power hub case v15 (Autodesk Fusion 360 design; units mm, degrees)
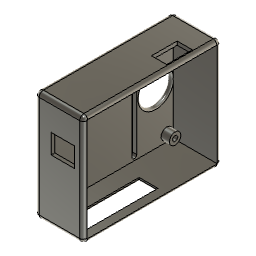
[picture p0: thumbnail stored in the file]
sketch "草图1" plane through (0, 0, 0) normal (1, 0, 0) x axis (0, 1, 0)
  line L1 (-27.76, -19.4335) -> (-27.76, 28.5665)
  line L2 (33.24, 28.5665) -> (33.24, -19.4335)
  line L3 (33.24, -19.4335) -> (-27.76, -19.4335)
  line L4 (-27.76, 28.5665) -> (33.24, 28.5665)
  line L5 (35.49, -21.6835) -> (-30.01, -21.6835)
  line L6 (35.49, 30.8165) -> (35.49, -21.6835)
  line L7 (-30.01, 30.8165) -> (35.49, 30.8165)
  line L8 (-30.01, -21.6835) -> (-30.01, 30.8165)
  line L9 (33.74, -19.9335) -> (-28.26, -19.9335)
  line L10 (33.74, 29.0665) -> (33.74, -19.9335)
  line L11 (-28.26, 29.0665) -> (33.74, 29.0665)
  line L12 (-28.26, -19.9335) -> (-28.26, 29.0665)
  circle C1 centre (30.68, -16.4685) radius 1.225
  circle C2 centre (-17.36, 25.6015) radius 1.225
  circle C3 centre (30.68, 25.6015) radius 1.225
  circle C4 centre (-17.36, -16.4685) radius 1.225
  point P2 (-27.76, 28.5665)
  point P3 (-27.76, -19.4335)
  point P5 (33.24, 28.5665)
  point P6 (-17.36, 25.6015)
  point P9 (30.68, 25.6015)
  point P7 (-17.36, -16.4685)
  point P8 (30.68, -16.4685)
  equal C2 C3
  equal C1 C3
  equal C1 C4
  dimension "d1" distance P2 P3 = 48
  dimension "d2" distance P2 P5 = 61 (= "57.00 mm + 4 mm")
  dimension "d3" distance P6 P9 = 48.04
  dimension "d4" distance P6 P7 = 42.07
  dimension "d5" distance P6 L4 = 2.965
  dimension "d6" distance P6 L1 = 10.4 (= "6.4 mm + 4 mm")
  dimension "d7" = 2.25
  dimension "d8" diameter C2 = 2.45
  dimension "d19" distance P7 P8 = 48.04
  dimension "d20" = 0.5
extrude "拉伸1" new body sketch "草图1" profile of C1 L1 L2 L3 C2 C3 L4 C4 along normal blind 2
extrude "拉伸2" add sketch "草图1" profile of L8 L5 L7 L6 L12 L11 L10 L9 along normal blind 23 (= "2.00 mm + 4 mm + 17 mm")
sketch "草图2" plane through (2, 0, 0) normal (1, 0, 0) x axis (0, 1, 0)
  line L1 (-28.26, -19.9335) -> (-28.26, 29.0665)
  line L2 (33.74, -19.9335) -> (-28.26, -19.9335)
  line L3 (33.74, 29.0665) -> (33.74, -19.9335)
  line L4 (-28.26, 29.0665) -> (33.74, 29.0665)
  circle C1 centre (-17.36, -16.4685) radius 1.225
  circle C2 centre (-17.36, 25.6015) radius 1.225
  circle C3 centre (30.68, 25.6015) radius 1.225
  circle C4 centre (30.68, -16.4685) radius 1.225
  circle C5 centre (-17.36, 25.6015) radius 2.725
  circle C6 centre (30.68, 25.6015) radius 2.725
  circle C7 centre (-17.36, -16.4685) radius 2.725
  circle C8 centre (30.68, -16.4685) radius 2.725
  dimension "d13" = 1.5
  dimension "d14" = 1.5
  dimension "d15" = 1.5
  dimension "d16" = 1.5
extrude "拉伸3" add sketch "草图2" profile of C1 C2 C3 C4 C5 C6 C7 C8 along normal blind 4
sketch "草图3" plane through (0, 0, -21.6835) normal (0, 0, -1) x axis (1, 0, 0)
  line L1 (0, -35.49) -> (0, 30.01)
  line L2 (23, -35.49) -> (0, -35.49)
  line L3 (23, 30.01) -> (23, -35.49)
  line L4 (0, 30.01) -> (23, 30.01)
  line L5 (6, 30.01) -> (6, -35.49)
  line L6 (6, -35.49) -> (23, -35.49)
  line L7 (23, 30.01) -> (23, -35.49)
  line L8 (23, 30.01) -> (6, 30.01)
  line L9 (19, 26.01) -> (10, 26.01)
  line L10 (19, 26.01) -> (19, -31.49)
  line L11 (10, -31.49) -> (19, -31.49)
  line L12 (10, 26.01) -> (10, -31.49)
  line L13 (10, -9.49) -> (19, -9.49)
  point P6 (6, -35.49)
  point P7 (6, 30.01)
  point P4 (23, -35.49)
  point P8 (23, -35.49)
  point P5 (23, 30.01)
  point P9 (23, 30.01)
  point P14 (19, -9.49)
  point P15 (10, -9.49)
  coincident L2 P6
  coincident L4 P7
  perpendicular L4 L5
  coincident P4 P8
  coincident P5 P9
  coincident L10 P14
  coincident L12 P15
  perpendicular L12 L13
  dimension "d21" distance L1 L5 = 6
  dimension "d22" = 4
  dimension "d25" distance L11 L13 = 22
extrude "拉伸4" cut sketch "草图3" profile of L10 L9 L12 L13 against normal blind 2
sketch "草图4" plane through (0, 0, 30.8165) normal (0, 0, 1) x axis (-1, 0, 0)
  line L1 (0, 30.01) -> (0, -35.49)
  line L2 (-23, 30.01) -> (0, 30.01)
  line L3 (-23, -35.49) -> (-23, 30.01)
  line L4 (0, -35.49) -> (-23, -35.49)
  line L5 (-18.8, -22.037) -> (-15.6, -22.037)
  line L6 (-18.8, -13.837) -> (-18.8, -22.037)
  line L7 (-15.6, -13.837) -> (-18.8, -13.837)
  line L8 (-15.6, -22.037) -> (-15.6, -13.837)
  line L9 (-13.6, -24.037) -> (-13.6, -11.837)
  line L10 (-20.8, -24.037) -> (-13.6, -24.037)
  line L11 (-20.8, -11.837) -> (-20.8, -24.037)
  line L12 (-13.6, -11.837) -> (-20.8, -11.837)
  point P6 (-15.6, -22.037)
  point P7 (-18.8, -22.037)
  point P8 (-18.8, -13.837)
  horizontal L5
  vertical L6
  horizontal L7
  vertical L8
  dimension "d26" distance L4 P6 = 13.453 (= "11.453 mm + 2 mm")
  dimension "d27" distance L1 L8 = 15.6 (= "9.6 mm + 4 mm + 2 mm")
  dimension "d28" distance P7 P8 = 8.2
  dimension "d29" distance P6 P7 = 3.2
  dimension "d30" = -2
extrude "拉伸5" cut sketch "草图4" profile of L9 L10 L11 L12 against normal blind 2
sketch "草图5" plane through (0, 0, 0) normal (-1, 0, 0) x axis (0, -1, 0)
  line L1 (30.01, 30.8165) -> (30.01, -21.6835)
  line L2 (-35.49, 30.8165) -> (30.01, 30.8165)
  line L3 (-35.49, -21.6835) -> (-35.49, 30.8165)
  line L4 (30.01, -21.6835) -> (-35.49, -21.6835)
  line L5 (-2.74, -21.6835) -> (-2.74, 30.8165)
  line L6 (30.01, 4.5665) -> (-2.74, 4.5665)
  line L7 (8.635, -17.9335) -> (8.635, 27.0665)
  line L8 (10.885, 27.0665) -> (10.885, -17.9335)
  line L9 (-16.365, 27.0665) -> (-16.365, -17.9335)
  line L10 (-14.115, -17.9335) -> (-14.115, 27.0665)
  line L11 (-25.49, 4.5665) -> (-2.74, 4.5665)
  circle C1 centre (-30.68, -16.4685) radius 1.225
  circle C2 centre (17.36, 25.6015) radius 1.225
  circle C3 centre (-30.68, 25.6015) radius 1.225
  circle C4 centre (17.36, -16.4685) radius 1.225
  circle C5 centre (9.76, 27.0665) radius 1.125
  circle C6 centre (9.76, -17.9335) radius 1.125
  circle C7 centre (-15.24, 27.0665) radius 1.125
  circle C8 centre (-15.24, -17.9335) radius 1.125
  circle C9 centre (-25.49, 4.5665) radius 7.5
  point P10 (-2.74, 30.8165)
  point P11 (-2.74, -21.6835)
  point P13 (-2.74, 4.5665)
  point P14 (30.01, 4.5665)
  point P16 (8.635, 27.0665)
  point P17 (8.635, -17.9335)
  point P18 (10.885, -17.9335)
  point P19 (10.885, 27.0665)
  point P15 (9.76, -17.9335)
  point P22 (-15.24, -17.9335)
  point P21 (-14.115, 27.0665)
  point P25 (-14.115, -17.9335)
  point P24 (-16.365, -17.9335)
  point P23 (-16.365, 27.0665)
  point P27 (-25.49, 4.5665)
  point P28 (-25.49, 4.5665)
  point P12 (9.76, 27.0665)
  point P20 (-15.24, 27.0665)
  midpoint L2 P10
  midpoint L4 P11
  midpoint L5 P13
  midpoint L1 P14
  symmetric C5 L6 C6
  coincident C5 P16
  coincident C6 P17
  coincident C6 P18
  coincident C5 P19
  vertical L8
  tangent C5 L8
  tangent C6 L7
  tangent C5 L7
  symmetric L5 C5 C7
  symmetric L5 P15 P22
  symmetric L5 P16 P21
  symmetric L5 P17 P25
  symmetric L5 P18 P24
  symmetric L5 P19 P23
  symmetric L5 C6 C8
  perpendicular L5 L11
  coincident P27 P28
  dimension "d33" diameter C5 = 2.25
  dimension "d34" distance P12 P20 = 25
  dimension "d35" distance P18 P19 = 45
  dimension "d38" diameter C9 = 15
  dimension "d39" distance L3 P28 = 10
extrude "拉伸6" cut sketch "草图5" profile of C5 C6 L7 L8 L9 C7 L10 C8 C9 against normal blind 2
sketch "草图6" plane through (0, -30.01, 0) normal (0, -1, 0) x axis (1, 0, 0)
  line L1 (0, -21.6835) -> (0, 30.8165)
  line L2 (23, -21.6835) -> (0, -21.6835)
  line L3 (23, 30.8165) -> (23, -21.6835)
  line L4 (0, 30.8165) -> (23, 30.8165)
  line L5 (18.8, 17.1985) -> (7.7, 17.1985)
  line L6 (18.8, 7.8895) -> (18.8, 17.1985)
  line L7 (7.7, 7.8895) -> (18.8, 7.8895)
  line L8 (7.7, 17.1985) -> (7.7, 7.8895)
  point P6 (7.7, 17.1985)
  point P7 (18.8, 17.1985)
  point P8 (18.8, 7.8895)
  horizontal L5
  vertical L6
  horizontal L7
  vertical L8
  dimension "d48" distance L4 L5 = 13.618 (= "11.368 mm + 2.25 mm")
  dimension "d49" distance P6 P7 = 11.1
  dimension "d50" distance P7 P8 = 9.309
  dimension "d51" distance L1 L8 = 7.7 (= "1.7 mm + 2 mm + 4 mm")
extrude "拉伸7" cut sketch "草图6" profile of L5 L6 L7 L8 against normal blind 1.75
fillet "圆角1" radius 2
fillet "圆角2" radius 1.74
fillet "圆角3" radius 1
fillet "圆角4" radius 1
fillet "圆角5" radius 1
